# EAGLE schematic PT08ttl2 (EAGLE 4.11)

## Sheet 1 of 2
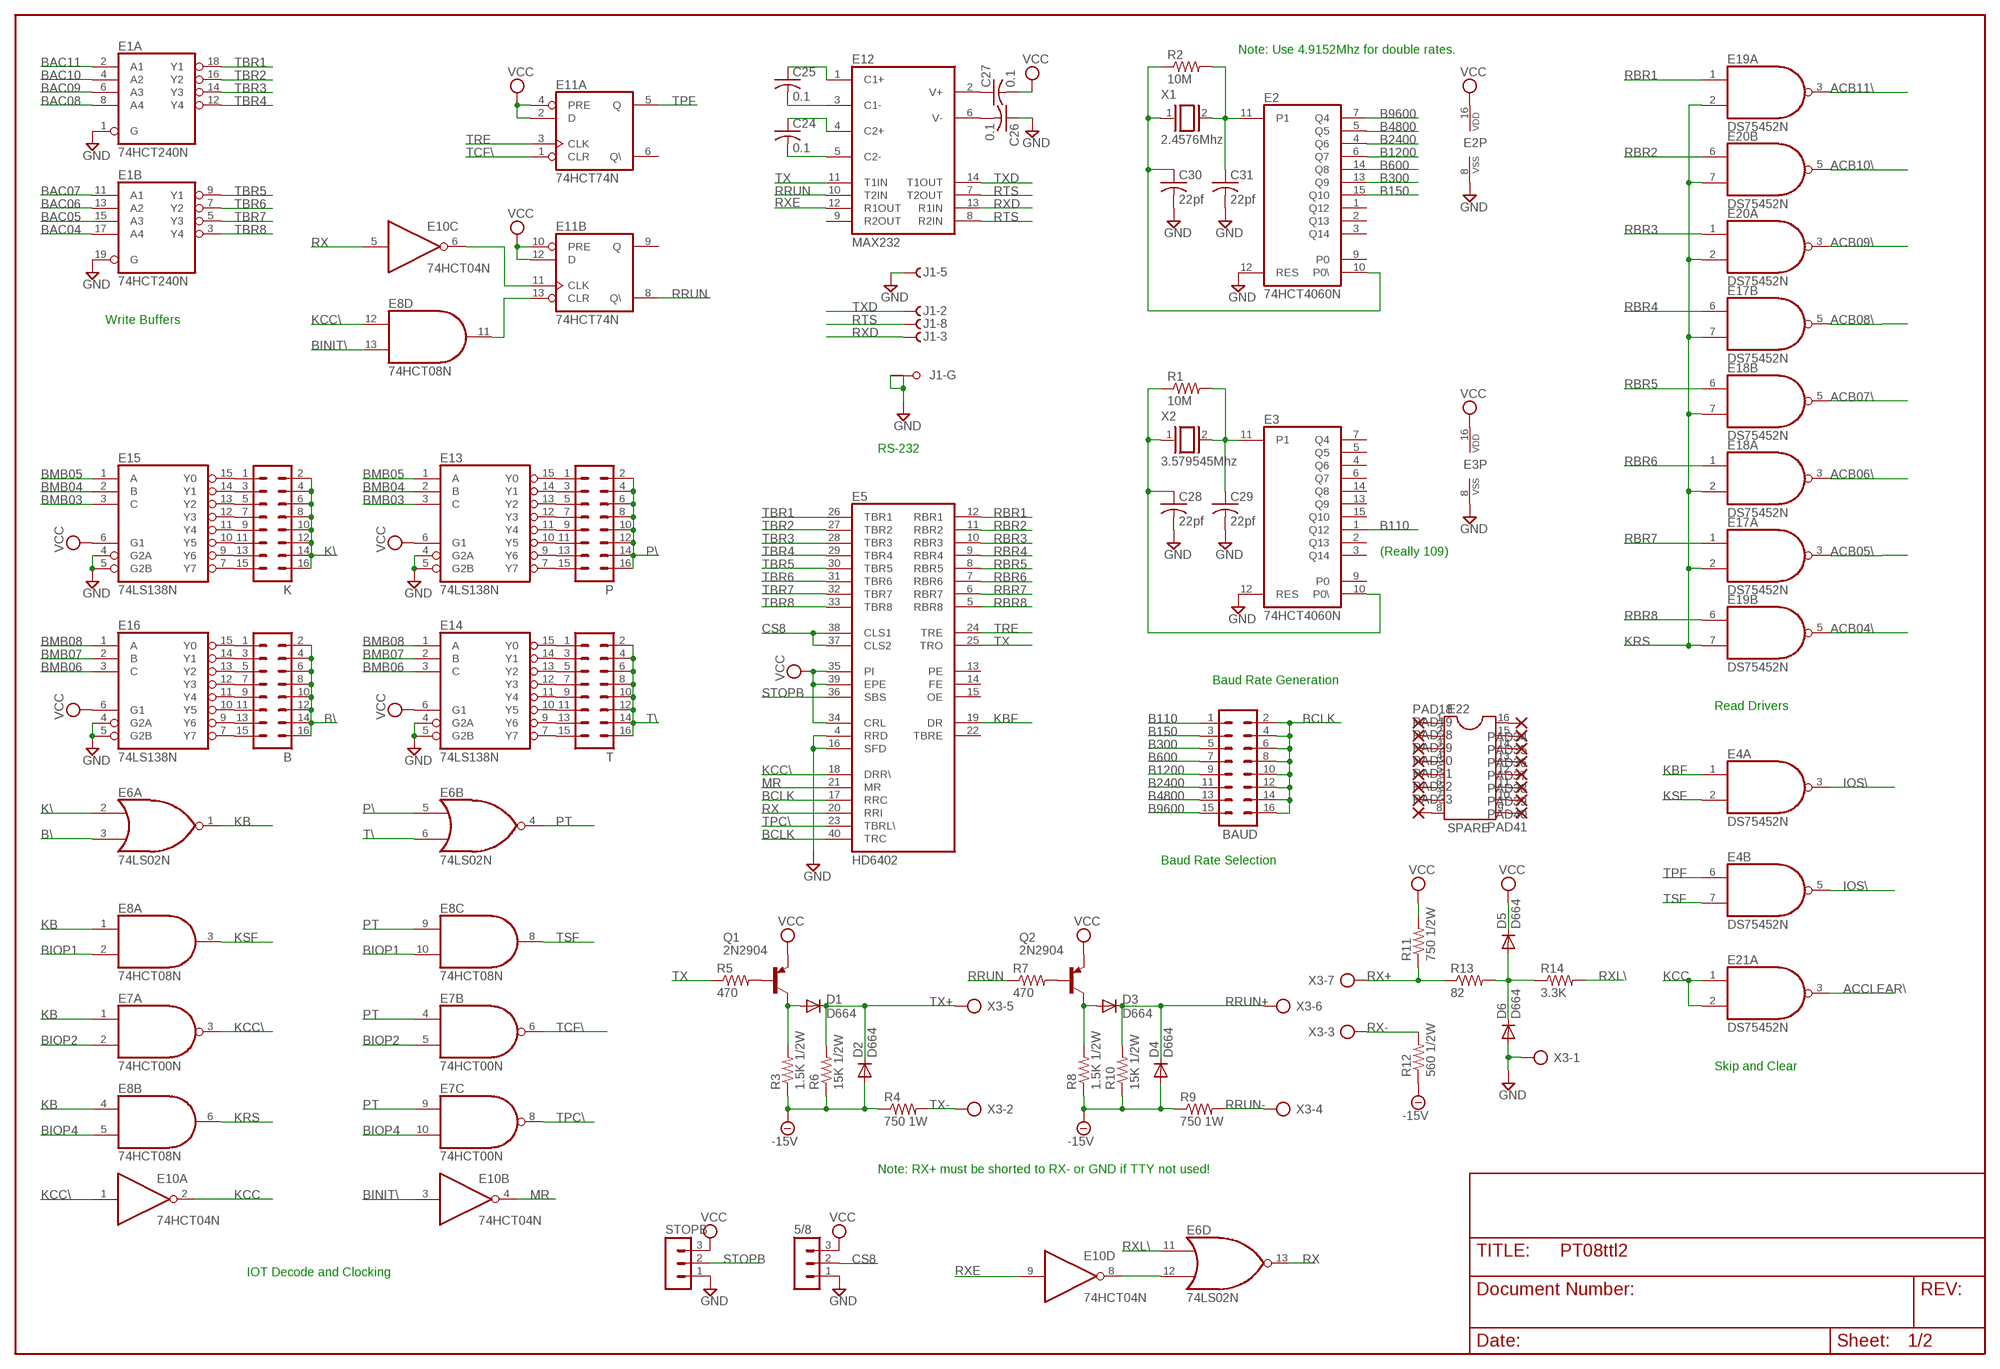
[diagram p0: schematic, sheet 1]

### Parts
5/8  MA03-1  [MA03-1]
B  MA08-2  [MA08-2]
BAUD  MA08-2  [MA08-2]
C24  0.1  C-US050-025X075  [C050-025X075]
C25  0.1  C-US050-025X075  [C050-025X075]
C26  0.1  C-US050-025X075  [C050-025X075]
C27  0.1  C-US050-025X075  [C050-025X075]
C28  22pf  C-US050-025X075  [C050-025X075]
C29  22pf  C-US050-025X075  [C050-025X075]
C30  22pf  C-US050-025X075  [C050-025X075]
C31  22pf  C-US050-025X075  [C050-025X075]
D1  D664  1N4148  [DO35-10]
D2  D664  1N4148  [DO35-10]
D3  D664  1N4148  [DO35-10]
D4  D664  1N4148  [DO35-10]
D5  D664  1N4148  [DO35-10]
D6  D664  1N4148  [DO35-10]
E1  74HCT240N  [DIL20]
E2  74HCT4060N  4060N  [DIL16]
E3  74HCT4060N  4060N  [DIL16]
E4  DS75452N  [DIL08]
E5  HD6402  [DIL40]
E6  74LS02N  [DIL14]
E7  74HCT00N  [DIL14]
E8  74HCT08N  [DIL14]
E10  74HCT04N  [DIL14]
E11  74HCT74N  [DIL14]
E12  MAX232  [DIL16]
E13  74LS138N  [DIL16]
E14  74LS138N  [DIL16]
E15  74LS138N  [DIL16]
E16  74LS138N  [DIL16]
E17  DS75452N  [DIL08]
E18  DS75452N  [DIL08]
E19  DS75452N  [DIL08]
E20  DS75452N  [DIL08]
E21  DS75452N  [DIL08]
E22  SPARE  DIL16  [DIL16]
J1  F09HPS  [F09HP]
K  MA08-2  [MA08-2]
P  MA08-2  [MA08-2]
PAD18  1,6/0,8  [1,6/0,8]
PAD19  1,6/0,8  [1,6/0,8]
PAD28  1,6/0,8  [1,6/0,8]
PAD29  1,6/0,8  [1,6/0,8]
PAD30  1,6/0,8  [1,6/0,8]
PAD31  1,6/0,8  [1,6/0,8]
PAD32  1,6/0,8  [1,6/0,8]
PAD33  1,6/0,8  [1,6/0,8]
PAD34  1,6/0,8  [1,6/0,8]
PAD35  1,6/0,8  [1,6/0,8]
PAD36  1,6/0,8  [1,6/0,8]
PAD37  1,6/0,8  [1,6/0,8]
PAD38  1,6/0,8  [1,6/0,8]
PAD39  1,6/0,8  [1,6/0,8]
PAD40  1,6/0,8  [1,6/0,8]
PAD41  1,6/0,8  [1,6/0,8]
Q1  2N2904  [TO39]
Q2  2N2904  [TO39]
R1  10M  R-US_0207/10  [0207/10]
R2  10M  R-US_0207/10  [0207/10]
R3  1.5K 1/2W  R-US_0207/10  [0207/10]
R4  750 1W  R-US_0207/10  [0207/10]
R5  470  R-US_0207/10  [0207/10]
R6  15K 1/2W  R-US_0207/10  [0207/10]
R7  470  R-US_0207/10  [0207/10]
R8  1.5K 1/2W  R-US_0207/10  [0207/10]
R9  750 1W  R-US_0207/10  [0207/10]
R10  15K 1/2W  R-US_0207/10  [0207/10]
R11  750 1/2W  R-US_0207/10  [0207/10]
R12  560 1/2W  R-US_0207/10  [0207/10]
R13  82  R-US_0207/10  [0207/10]
R14  3.3K  R-US_0207/10  [0207/10]
STOPB  MA03-1  [MA03-1]
T  MA08-2  [MA08-2]
X1  2.4576Mhz  XTAL/S  [QS]
X2  3.579545Mhz  XTAL/S  [QS]
X3  AK300/7  [AK300/7]

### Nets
-15V [supply]: D2.A D4.A R3.1 R4.1 R6.1 R8.1 R9.1 R10.1 R12.1 ; also sheet 2
ACB04\: E19.5(B:O) ; also sheet 2
ACB05\: E17.3(A:O) ; also sheet 2
ACB06\: E18.3(A:O) ; also sheet 2
ACB07\: E18.5(B:O) ; also sheet 2
ACB08\: E17.5(B:O) ; also sheet 2
ACB09\: E20.3(A:O) ; also sheet 2
ACB10\: E20.5(B:O) ; also sheet 2
ACB11\: E19.3(A:O) ; also sheet 2
ACCLEAR\: E21.3(A:O) ; also sheet 2
B110: BAUD.1 E3.1(Q12)
B150: BAUD.3 E2.15(Q10)
B300: BAUD.5 E2.13(Q9)
B600: BAUD.7 E2.14(Q8)
B1200: BAUD.9 E2.6(Q7)
B2400: BAUD.11 E2.4(Q6)
B4800: BAUD.13 E2.5(Q5)
B9600: BAUD.15 E2.7(Q4)
B\: B.2 B.4 B.6 B.8 B.10 B.12 B.14 B.16 E6.3(A:I1)
BAC04: E1.17(B:A4) ; also sheet 2
BAC05: E1.15(B:A3) ; also sheet 2
BAC06: E1.13(B:A2) ; also sheet 2
BAC07: E1.11(B:A1) ; also sheet 2
BAC08: E1.8(A:A4) ; also sheet 2
BAC09: E1.6(A:A3) ; also sheet 2
BAC10: E1.4(A:A2) ; also sheet 2
BAC11: E1.2(A:A1) ; also sheet 2
BCLK: BAUD.2 BAUD.4 BAUD.6 BAUD.8 BAUD.10 BAUD.12 BAUD.14 BAUD.16 E5.17(RRC) E5.40(TRC)
BINIT\: E8.13(D:I1) E10.3(B:I) ; also sheet 2
BIOP1: E8.2(A:I1) E8.10(C:I1) ; also sheet 2
BIOP2: E7.2(A:I1) E7.5(B:I1) ; also sheet 2
BIOP4: E7.10(C:I1) E8.5(B:I1) ; also sheet 2
BMB03: E13.3(C) E15.3(C) ; also sheet 2
BMB04: E13.2(B) E15.2(B) ; also sheet 2
BMB05: E13.1(A) E15.1(A) ; also sheet 2
BMB06: E14.3(C) E16.3(C) ; also sheet 2
BMB07: E14.2(B) E16.2(B) ; also sheet 2
BMB08: E14.1(A) E16.1(A) ; also sheet 2
CS8: 5/8.2 E5.37(CLS2) E5.38(CLS1)
GND [supply]: 5/8.1 C26.1 C28.2 C29.2 C30.2 C31.2 D6.A E1.1(A:G) E1.19(B:G) E2.8(VSS) E2.12(RES) E3.8(VSS) E3.12(RES) E5.4(RRD) E5.16(SFD) E13.4(G2A) E13.5(G2B) E14.4(G2A) E14.5(G2B) E15.4(G2A) E15.5(G2B) E16.4(G2A) E16.5(G2B) J1.5(-5:F) J1.G1(-G:G1) J1.G2(-G:G2) STOPB.1 X3.1 ; also sheet 2
IOS\: E4.3(A:O) E4.5(B:O) ; also sheet 2
K\: E6.2(A:I0) K.2 K.4 K.6 K.8 K.10 K.12 K.14 K.16
KB: E6.1(A:O) E7.1(A:I0) E8.1(A:I0) E8.4(B:I0)
KBF: E4.1(A:I0) E5.19(DR)
KCC: E10.2(A:O) E21.1(A:I0) E21.2(A:I1)
KCC\: E5.18(DRR\) E7.3(A:O) E8.12(D:I0) E10.1(A:I)
KRS: E8.6(B:O) E17.2(A:I1) E17.7(B:I1) E18.2(A:I1) E18.7(B:I1) E19.2(A:I1) E19.7(B:I1) E20.2(A:I1) E20.7(B:I1)
KSF: E4.2(A:I1) E8.3(A:O)
MR: E5.21(MR) E10.4(B:O)
N$1: B.13 E16.9(Y6)
N$5: B.1 E16.15(Y0)
N$6: B.3 E16.14(Y1)
N$7: B.5 E16.13(Y2)
N$8: B.7 E16.12(Y3)
N$9: B.9 E16.11(Y4)
N$10: B.11 E16.10(Y5)
N$11: B.15 E16.7(Y7)
N$13: C29.1 E3.11(P1) R1.2 X2.2
N$14: C28.1 E3.10(P0\) R1.1 X2.1
N$15 [supply]: C26.2 E12.6(V-)
N$16 [supply]: C27.1 E12.2(V+)
N$17: Q1.2(B) R5.2
N$18: D1.A Q1.3(C) R3.2
N$19: Q2.2(B) R7.2
N$20: D3.A Q2.3(C) R8.2
N$22: C24.2 E12.5(C2-)
N$23: C30.1 E2.10(P0\) R2.1 X1.1
N$24: D5.A D6.C R13.2 R14.1
N$25: C31.1 E2.11(P1) R2.2 X1.2
N$26: E8.11(D:O) E11.13(B:CLR)
N$27: E6.12(D:I1) E10.8(D:O)
N$29: E10.6(C:O) E11.11(B:CLK)
N$32: C25.2 E12.3(C1-)
N$34: E22.1 PAD18.1(P)
N$41: E22.2 PAD19.1(P)
N$43: E22.3 PAD28.1(P)
N$44: C24.1 E12.4(C2+)
N$45: C25.1 E12.1(C1+)
N$49: E14.15(Y0) T.1
N$50: E22.4 PAD29.1(P)
N$51: E22.5 PAD30.1(P)
N$52: E22.6 PAD31.1(P)
N$53: E22.7 PAD32.1(P)
N$54: E22.8 PAD33.1(P)
N$55: E22.16 PAD34.1(P)
N$56: E22.15 PAD35.1(P)
N$57: E22.14 PAD36.1(P)
N$58: E22.13 PAD37.1(P)
N$59: E22.12 PAD38.1(P)
N$61: E22.11 PAD39.1(P)
N$68: E22.10 PAD40.1(P)
N$69: E22.9 PAD41.1(P)
N$90: E15.15(Y0) K.1
N$91: E15.14(Y1) K.3
N$97: E15.13(Y2) K.5
N$109: E15.12(Y3) K.7
N$112: E15.11(Y4) K.9
N$113: E15.10(Y5) K.11
N$114: E15.7(Y7) K.15
N$115: E15.9(Y6) K.13
N$116: E14.14(Y1) T.3
N$117: E14.13(Y2) T.5
N$118: E14.12(Y3) T.7
N$119: E14.11(Y4) T.9
N$120: E14.10(Y5) T.11
N$121: E14.7(Y7) T.15
N$122: E14.9(Y6) T.13
N$123: E13.15(Y0) P.1
N$124: E13.14(Y1) P.3
N$125: E13.13(Y2) P.5
N$126: E13.12(Y3) P.7
N$127: E13.11(Y4) P.9
N$128: E13.10(Y5) P.11
N$129: E13.7(Y7) P.15
N$130: E13.9(Y6) P.13
P\: E6.5(B:I0) P.2 P.4 P.6 P.8 P.10 P.12 P.14 P.16
PT: E6.4(B:O) E7.4(B:I0) E7.9(C:I0) E8.9(C:I0)
RBR1: E5.12(RBR1) E19.1(A:I0)
RBR2: E5.11(RBR2) E20.6(B:I0)
RBR3: E5.10(RBR3) E20.1(A:I0)
RBR4: E5.9(RBR4) E17.6(B:I0)
RBR5: E5.8(RBR5) E18.6(B:I0)
RBR6: E5.7(RBR6) E18.1(A:I0)
RBR7: E5.6(RBR7) E17.1(A:I0)
RBR8: E5.5(RBR8) E19.6(B:I0)
RRUN: E11.8(B:Q\) E12.10(T2IN) R7.1
RRUN+: D3.C D4.C R10.2 X3.6
RRUN-: R9.2 X3.4
RTS: E12.7(T2OUT) E12.8(R2IN) J1.8(-8:F)
RX: E5.20(RRI) E6.13(D:O) E10.5(C:I)
RX+: R11.1 R13.1 X3.7
RX-: R12.2 X3.3
RXD: E12.13(R1IN) J1.3(-3:F)
RXE: E10.9(D:I) E12.12(R1OUT)
RXL\: E6.11(D:I0) R14.2
STOPB: E5.36(SBS) STOPB.2
T\: E6.6(B:I1) T.2 T.4 T.6 T.8 T.10 T.12 T.14 T.16
TBR1: E1.18(A:Y1) E5.26(TBR1)
TBR2: E1.16(A:Y2) E5.27(TBR2)
TBR3: E1.14(A:Y3) E5.28(TBR3)
TBR4: E1.12(A:Y4) E5.29(TBR4)
TBR5: E1.9(B:Y1) E5.30(TBR5)
TBR6: E1.7(B:Y2) E5.31(TBR6)
TBR7: E1.5(B:Y3) E5.32(TBR7)
TBR8: E1.3(B:Y4) E5.33(TBR8)
TCF\: E7.6(B:O) E11.1(A:CLR)
TPC\: E5.23(TBRL\) E7.8(C:O)
TPF: E4.6(B:I0) E11.5(A:Q)
TRE: E5.24(TRE) E11.3(A:CLK)
TSF: E4.7(B:I1) E8.8(C:O)
TX: E5.25(TRO) E12.11(T1IN) R5.1
TX+: D1.C D2.C R6.2 X3.5
TX-: R4.2 X3.2
TXD: E12.14(T1OUT) J1.2(-2:F)
VCC [supply]: 5/8.3 C27.2 D5.C E2.16(VDD) E3.16(VDD) E5.34(CRL) E5.35(PI) E5.39(EPE) E11.2(A:D) E11.4(A:PRE) E11.10(B:PRE) E11.12(B:D) E13.6(G1) E14.6(G1) E15.6(G1) E16.6(G1) Q1.1(E) Q2.1(E) R11.2 STOPB.3 ; also sheet 2
Unconnected: E2.1(Q12) E2.2(Q13) E2.3(Q14) E2.9(P0) E3.2(Q13) E3.3(Q14) E3.4(Q6) E3.5(Q5) E3.6(Q7) E3.7(Q4) E3.9(P0) E3.13(Q9) E3.14(Q8) E3.15(Q10) E5.13(PE) E5.14(FE) E5.15(OE) E5.22(TBRE) E11.6(A:Q\) E11.9(B:Q) E12.9(R2OUT) J1.1(-1:F) J1.4(-4:F) J1.6(-6:F) J1.7(-7:F) J1.9(-9:F)

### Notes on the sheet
- Note: Use 4.9152Mhz for double rates.
- Write Buffers
- RS-232
- (Really 109)
- Baud Rate Generation
- Read Drivers
- Baud Rate Selection
- Skip and Clear
- Note: RX+ must be shorted to RX- or GND if TTY not used!
- IOT Decode and Clocking

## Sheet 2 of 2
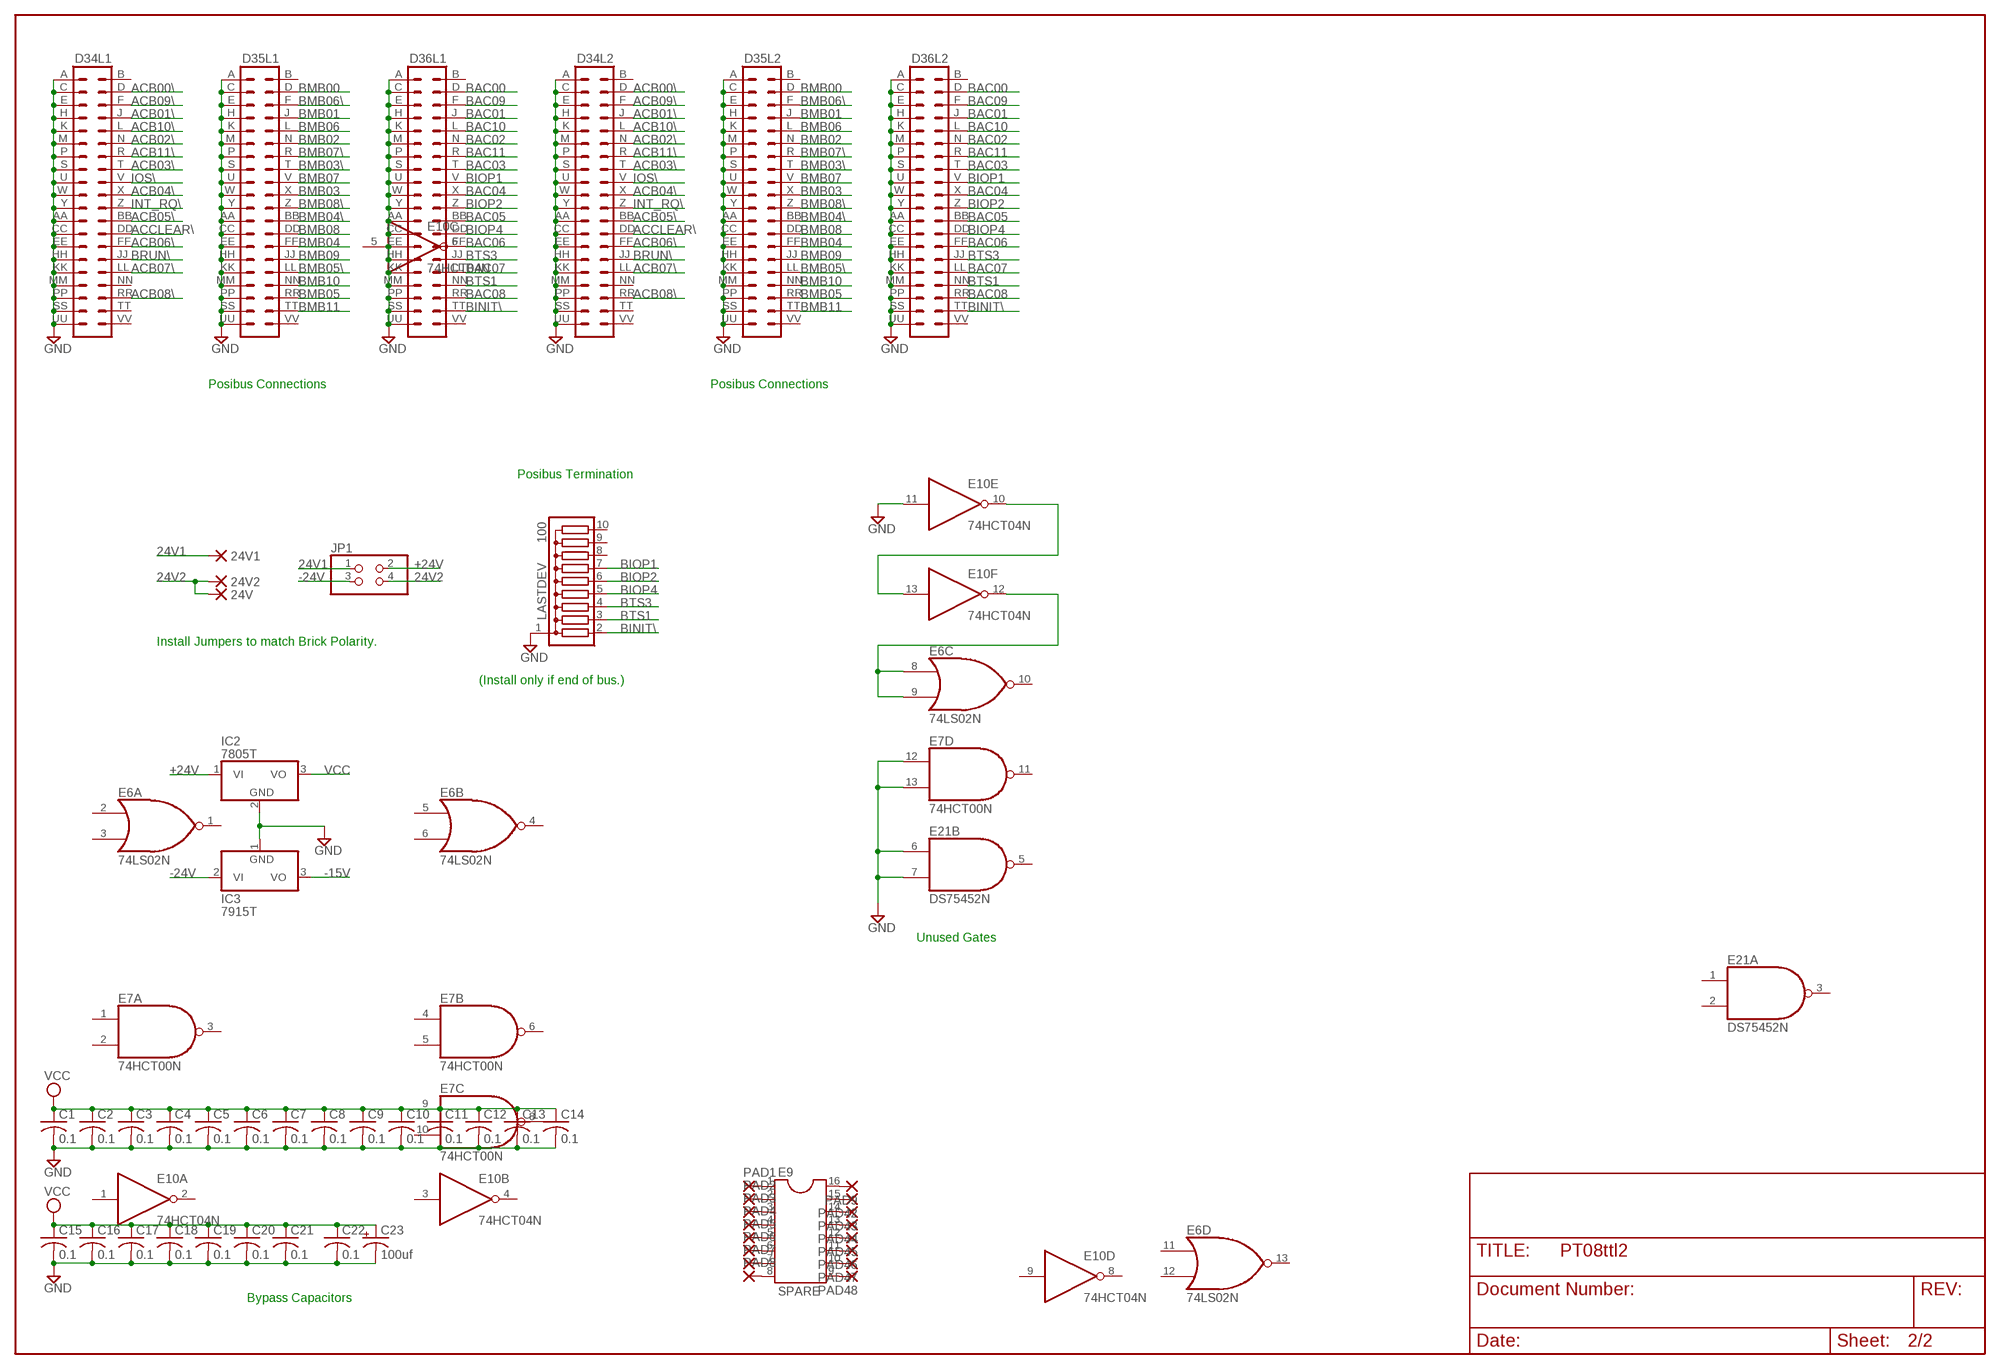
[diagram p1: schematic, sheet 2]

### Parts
24V  PAD-0820  [0820]
24V1  PAD-0820  [0820]
24V2  PAD-0820  [0820]
C1  0.1  C-US050-025X075  [C050-025X075]
C2  0.1  C-US050-025X075  [C050-025X075]
C3  0.1  C-US050-025X075  [C050-025X075]
C4  0.1  C-US050-025X075  [C050-025X075]
C5  0.1  C-US050-025X075  [C050-025X075]
C6  0.1  C-US050-025X075  [C050-025X075]
C7  0.1  C-US050-025X075  [C050-025X075]
C8  0.1  C-US050-025X075  [C050-025X075]
C9  0.1  C-US050-025X075  [C050-025X075]
C10  0.1  C-US050-025X075  [C050-025X075]
C11  0.1  C-US050-025X075  [C050-025X075]
C12  0.1  C-US050-025X075  [C050-025X075]
C13  0.1  C-US050-025X075  [C050-025X075]
C14  0.1  C-US050-025X075  [C050-025X075]
C15  0.1  C-US050-025X075  [C050-025X075]
C16  0.1  C-US050-025X075  [C050-025X075]
C17  0.1  C-US050-025X075  [C050-025X075]
C18  0.1  C-US050-025X075  [C050-025X075]
C19  0.1  C-US050-025X075  [C050-025X075]
C20  0.1  C-US050-025X075  [C050-025X075]
C21  0.1  C-US050-025X075  [C050-025X075]
C22  0.1  C-US050-025X075  [C050-025X075]
C23  100uf  CPOL-USE22-9AXIAL  [E22-9]
D34L1  DEC40PIN  [DEC40PIN]
D34L2  DEC40PIN  [DEC40PIN]
D35L1  DEC40PIN  [DEC40PIN]
D35L2  DEC40PIN  [DEC40PIN]
D36L1  DEC40PIN  [DEC40PIN]
D36L2  DEC40PIN  [DEC40PIN]
E9  SPARE  DIL16  [DIL16]
IC2  7805T  [TO220H]
IC3  7915T  [TO220H]
JP1  PINHD-2X2  [2X02]
LASTDEV  100  G09R  [SIL10]
PAD1  1,6/0,8  [1,6/0,8]
PAD2  1,6/0,8  [1,6/0,8]
PAD3  1,6/0,8  [1,6/0,8]
PAD4  1,6/0,8  [1,6/0,8]
PAD5  1,6/0,8  [1,6/0,8]
PAD6  1,6/0,8  [1,6/0,8]
PAD7  1,6/0,8  [1,6/0,8]
PAD8  1,6/0,8  [1,6/0,8]
PAD9  1,6/0,8  [1,6/0,8]
PAD42  1,6/0,8  [1,6/0,8]
PAD43  1,6/0,8  [1,6/0,8]
PAD44  1,6/0,8  [1,6/0,8]
PAD45  1,6/0,8  [1,6/0,8]
PAD46  1,6/0,8  [1,6/0,8]
PAD47  1,6/0,8  [1,6/0,8]
PAD48  1,6/0,8  [1,6/0,8]

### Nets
24V1 [supply]: 24V1.P$1(P) JP1.1
24V2 [supply]: 24V2.P$1(P) 24V.P$1(P) JP1.4
+24V [supply]: IC2.1(VI) JP1.2
-15V [supply]: IC3.3(VO) ; also sheet 1
-24V [supply]: IC3.2(VI) JP1.3
ACB00\: D34L1.D D34L2.D
ACB01\: D34L1.J D34L2.J
ACB02\: D34L1.N D34L2.N
ACB03\: D34L1.T D34L2.T
ACB04\: D34L1.X D34L2.X ; also sheet 1
ACB05\: D34L1.BB D34L2.BB ; also sheet 1
ACB06\: D34L1.FF D34L2.FF ; also sheet 1
ACB07\: D34L1.LL D34L2.LL ; also sheet 1
ACB08\: D34L1.RR D34L2.RR ; also sheet 1
ACB09\: D34L1.F D34L2.F ; also sheet 1
ACB10\: D34L1.L D34L2.L ; also sheet 1
ACB11\: D34L1.R D34L2.R ; also sheet 1
ACCLEAR\: D34L1.DD D34L2.DD ; also sheet 1
BAC00: D36L1.D D36L2.D
BAC01: D36L1.J D36L2.J
BAC02: D36L1.N D36L2.N
BAC03: D36L1.T D36L2.T
BAC04: D36L1.X D36L2.X ; also sheet 1
BAC05: D36L1.BB D36L2.BB ; also sheet 1
BAC06: D36L1.FF D36L2.FF ; also sheet 1
BAC07: D36L1.LL D36L2.LL ; also sheet 1
BAC08: D36L1.RR D36L2.RR ; also sheet 1
BAC09: D36L1.F D36L2.F ; also sheet 1
BAC10: D36L1.L D36L2.L ; also sheet 1
BAC11: D36L1.R D36L2.R ; also sheet 1
BINIT\: D36L1.TT D36L2.TT LASTDEV.2 ; also sheet 1
BIOP1: D36L1.V D36L2.V LASTDEV.7 ; also sheet 1
BIOP2: D36L1.Z D36L2.Z LASTDEV.6 ; also sheet 1
BIOP4: D36L1.DD D36L2.DD LASTDEV.5 ; also sheet 1
BMB00: D35L1.D D35L2.D
BMB01: D35L1.J D35L2.J
BMB02: D35L1.N D35L2.N
BMB03: D35L1.X D35L2.X ; also sheet 1
BMB03\: D35L1.T D35L2.T
BMB04: D35L1.FF D35L2.FF ; also sheet 1
BMB04\: D35L1.BB D35L2.BB
BMB05: D35L1.RR D35L2.RR ; also sheet 1
BMB05\: D35L1.LL D35L2.LL
BMB06: D35L1.L D35L2.L ; also sheet 1
BMB06\: D35L1.F D35L2.F
BMB07: D35L1.V D35L2.V ; also sheet 1
BMB07\: D35L1.R D35L2.R
BMB08: D35L1.DD D35L2.DD ; also sheet 1
BMB08\: D35L1.Z D35L2.Z
BMB09: D35L1.JJ D35L2.JJ
BMB10: D35L1.NN D35L2.NN
BMB11: D35L1.TT D35L2.TT
BRUN\: D34L1.JJ D34L2.JJ
BTS1: D36L1.NN D36L2.NN LASTDEV.3
BTS3: D36L1.JJ D36L2.JJ LASTDEV.4
GND [supply]: C1.2 C2.2 C3.2 C4.2 C5.2 C6.2 C7.2 C8.2 C9.2 C10.2 C11.2 C12.2 C13.2 C14.2 C15.2 C16.2 C17.2 C18.2 C19.2 C20.2 C21.2 C22.2 C23.- D34L1.A D34L1.AA D34L1.C D34L1.CC D34L1.E D34L1.EE D34L1.H D34L1.HH D34L1.K D34L1.KK D34L1.M D34L1.MM D34L1.P D34L1.PP D34L1.S D34L1.SS D34L1.U D34L1.UU D34L1.W D34L1.Y D34L2.A D34L2.AA D34L2.C D34L2.CC D34L2.E D34L2.EE D34L2.H D34L2.HH D34L2.K D34L2.KK D34L2.M D34L2.MM D34L2.P D34L2.PP D34L2.S D34L2.SS D34L2.U D34L2.UU D34L2.W D34L2.Y D35L1.A D35L1.AA D35L1.C D35L1.CC D35L1.E D35L1.EE D35L1.H D35L1.HH D35L1.K D35L1.KK D35L1.M D35L1.MM D35L1.P D35L1.PP D35L1.S D35L1.SS D35L1.U D35L1.UU D35L1.W D35L1.Y D35L2.A D35L2.AA D35L2.C D35L2.CC D35L2.E D35L2.EE D35L2.H D35L2.HH D35L2.K D35L2.KK D35L2.M D35L2.MM D35L2.P D35L2.PP D35L2.S D35L2.SS D35L2.U D35L2.UU D35L2.W D35L2.Y D36L1.A D36L1.AA D36L1.C D36L1.CC D36L1.E D36L1.EE D36L1.H D36L1.HH D36L1.K D36L1.KK D36L1.M D36L1.MM D36L1.P D36L1.PP D36L1.S D36L1.SS D36L1.U D36L1.UU D36L1.W D36L1.Y D36L2.A D36L2.AA D36L2.C D36L2.CC D36L2.E D36L2.EE D36L2.H D36L2.HH D36L2.K D36L2.KK D36L2.M D36L2.MM D36L2.P D36L2.PP D36L2.S D36L2.SS D36L2.U D36L2.UU D36L2.W D36L2.Y E7.12(D:I0) E7.13(D:I1) E10.11(E:I) E21.6(B:I0) E21.7(B:I1) IC2.2(GND) IC3.1(GND) LASTDEV.1 ; also sheet 1
INT_RQ\: D34L1.Z D34L2.Z
IOS\: D34L1.V D34L2.V ; also sheet 1
N$2: E9.1 PAD1.1(P)
N$3: E9.2 PAD2.1(P)
N$4: E9.3 PAD3.1(P)
N$12: E9.4 PAD4.1(P)
N$21: E9.5 PAD5.1(P)
N$30 [supply]: E10.10(E:O) E10.13(F:I)
N$31: E9.6 PAD6.1(P)
N$33: E9.7 PAD7.1(P)
N$35: E9.8 PAD8.1(P)
N$37: E9.16 PAD9.1(P)
N$38: E9.15 PAD42.1(P)
N$39: E9.14 PAD43.1(P)
N$40: E9.13 PAD44.1(P)
N$42: E9.12 PAD45.1(P)
N$46: E9.11 PAD46.1(P)
N$47: E9.10 PAD47.1(P)
N$48: E9.9 PAD48.1(P)
N$60 [supply]: E6.8(C:I0) E6.9(C:I1) E10.12(F:O)
VCC [supply]: C1.1 C2.1 C3.1 C4.1 C5.1 C6.1 C7.1 C8.1 C9.1 C10.1 C11.1 C12.1 C13.1 C14.1 C15.1 C16.1 C17.1 C18.1 C19.1 C20.1 C21.1 C22.1 C23.+ IC2.3(VO) ; also sheet 1
Unconnected: D34L1.B D34L1.NN D34L1.TT D34L1.VV D34L2.B D34L2.NN D34L2.TT D34L2.VV D35L1.B D35L1.VV D35L2.B D35L2.VV D36L1.B D36L1.VV D36L2.B D36L2.VV E6.10(C:O) E7.11(D:O) E21.5(B:O) LASTDEV.8 LASTDEV.9 LASTDEV.10

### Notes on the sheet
- Posibus Connections | Posibus Connections
- Posibus Termination
- Install Jumpers to match Brick Polarity.
- (Install only if end of bus.)
- Unused Gates
- Bypass Capacitors

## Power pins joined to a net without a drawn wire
GND: E1.10(P:GND) E4.4(P:GND) E5.3(GND) E6.7(P:GND) E7.7(P:GND) E8.7(P:GND) E10.7(P:GND) E11.7(P:GND) E12.15(GND) E13.8(GND) E14.8(GND) E15.8(GND) E16.8(GND) E17.4(P:GND) E18.4(P:GND) E19.4(P:GND) E20.4(P:GND) E21.4(P:GND)
VCC: E1.20(P:VCC) E4.8(P:VCC) E5.1(VCC) E6.14(P:VCC) E7.14(P:VCC) E8.14(P:VCC) E10.14(P:VCC) E11.14(P:VCC) E12.16(VCC) E13.16(VCC) E14.16(VCC) E15.16(VCC) E16.16(VCC) E17.8(P:VCC) E18.8(P:VCC) E19.8(P:VCC) E20.8(P:VCC) E21.8(P:VCC)

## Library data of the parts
5/8 STOPB = con-lstb:MA03-1: PIN HEADER
24V 24V1 24V2 = dpads:PAD: WIRE PAD
B BAUD K P T = con-lstb:MA08-2: PIN HEADER
C1-C22 C24-C31 = rcl:C-US: CAPACITOR, American symbol
C23 = rcl:CPOL-US: POLARIZED CAPACITOR, American symbol
D1-D6 = diode:1N4148: DIODE
D34L1 D34L2 D35L1 D35L2 D36L1 D36L2 = dec-con:DEC40PIN: PIN HEADER
E1 = 74xx-jameco:74*240: Octal BUFFER and LINE DRIVER, 3-state
E2 E3 = 40xx:4060: 14-stage binary/ripple COUNTER
E4 E17-E21 = 74xx-jameco:DS75452: Quad 2-input NAND gate, open collector output
E5 = micro-harris:HD6402: MICROCONTROLLER/MEMORY DEVICE
E6 = 74xx-us:74*02: Quad 2-input NOR gate
E7 = 74xx-jameco:74*00: Quad 2-input NAND gate
E8 = 74xx-jameco:74*08: Quad 2-input AND gate
E9 E22 = ic-package:DIL16: Dual In Line
E10 = 74xx-jameco:74*04: Hex INVERTER
E11 = 74xx-jameco:74*74: Dual D type positive edge triggered FLIP FLOP, preset and clear
E12 = maxim:MAX232: RS232 TRANSEIVER
E13-E16 = 74xx-jameco:74*138: 3-line to 8-line DECODER/DEMULTIPLEXER
IC2 = linear:78*: Positive VOLTAGE REGULATOR
IC3 = linear:79*: Negative VOLTAGE REGULATOR
J1 = con-subd:F09HPS: SUB-D
JP1 = pinhead:PINHD-2X2: PIN HEADER
LASTDEV = resistor-sil:G09R: SIL RESISTOR
PAD1-PAD9 PAD18 PAD19 PAD28-PAD48 = wirepad:1,6/0,8: THROUGH-HOLE PAD
Q1 Q2 = transistor-pnp:2N2904*: PNP Transistror
R1-R14 = rcl:R-US_: RESISTOR, American symbol
X1 X2 = special:XTAL/S: CRYSTAL
X3 = con-ptr500:AK300/7: CONNECTOR

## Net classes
1 supply: width 0.508 mm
